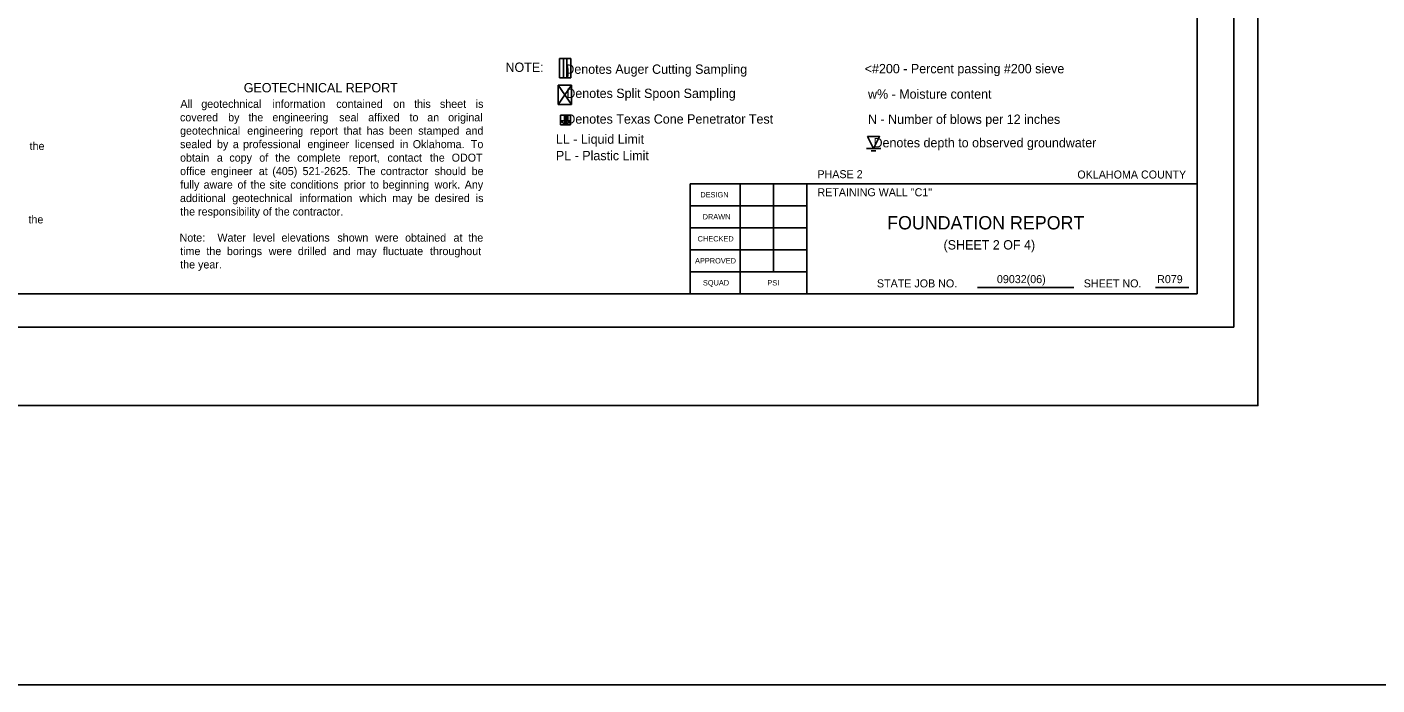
# Model space of a CAD drawing. Extents: x -6 to 173, y 24 to 64.
# Drawn here: x 65.85 to 86.09, y 25.78 to 35.64 of the extents above; entities that cross this region are included whole.
import ezdxf

# ---------------------------------------------------------------- set-up
doc = ezdxf.new("R2010")
doc.units = 0
for name, color, linetype in [('4', 7, 'Continuous'), ('S', 7, 'Continuous'), ('SHT_Plot_Shape_Full', 7, 'Continuous'), ('SHT_Plot_Shape_Half', 7, 'Continuous'), ('SHT_Sheet_Border', 7, 'Continuous'), ('SHT_Standard_Sheet_Lines', 7, 'Continuous'), ('SHT_Standard_Sheet_Txt', 7, 'Continuous'), ('T', 7, 'Continuous'), ('T-5', 7, 'Continuous'), ('Text', 7, 'Continuous')]:
    doc.layers.add(name, color=color, linetype=linetype)

# ---------------------------------------------------------------- blocks, each defined once
blk = doc.blocks.new('DGRFC_WTLEV1_1')
for points in [[(-0.005, 0), (0.005, 0)], [(0, 0), (0.00417, 0.00833), (-0.00417, 0.00833), (0, 0)], [(-0.00167, -0.00167), (0.00167, -0.00167)]]:
    blk.add_lwpolyline(points)

msp = doc.modelspace()

# ---------------------------------------------------------------- linework, layer by layer
msp.add_line((73.832, 35.172), (73.832, 34.881))
for points in [[(73.832, 35.172), (73.999, 35.172)], [(73.999, 34.881), (73.999, 35.172)], [(73.832, 34.881), (73.999, 34.881)], [(73.832, 34.881), (73.999, 34.881)]]:
    msp.add_lwpolyline(points)
for points in [[(73.891, 35.172), (73.891, 34.881), (73.941, 34.881), (73.941, 35.172)], [(73.955, 35.005), (73.949, 35.047), (73.941, 35.087), (73.955, 35.005)], [(73.941, 35.087), (73.941, 34.881), (73.955, 35.005), (73.941, 35.087)], [(73.941, 34.881), (73.955, 34.922), (73.955, 35.005), (73.941, 34.881)], [(73.941, 34.881), (73.949, 34.881), (73.955, 34.922), (73.941, 34.881)], [(73.955, 34.922), (73.957, 34.963), (73.955, 35.005), (73.955, 34.922)]]:
    msp.add_lwpolyline(points, close=True)
at = {"layer": 'S'}
msp.add_lwpolyline([(-6.024, 64.421), (172.576, 64.421), (172.576, 25.783), (-6.024, 25.783)], close=True, dxfattribs=at)
at = {"layer": 'SHT_Plot_Shape_Full'}
msp.add_lwpolyline([(48.302, 53.971), (84.302, 53.971), (84.302, 29.971), (48.302, 29.971)], close=True, dxfattribs=at)
at = {"layer": 'SHT_Plot_Shape_Half'}
msp.add_lwpolyline([(49.939, 53.146), (83.939, 53.146), (83.939, 31.146), (49.939, 31.146)], close=True, dxfattribs=at)
at = {"layer": 'SHT_Sheet_Border'}
for p, q in [((75.789, 31.646), (75.789, 33.296)), ((75.789, 33.296), (83.389, 33.296)), ((77.539, 31.646), (77.539, 33.297))]:
    msp.add_line(p, q, dxfattribs=at)
msp.add_lwpolyline([(51.889, 52.646), (83.389, 52.646), (83.389, 31.646), (51.889, 31.646)], close=True, dxfattribs=at)
at = {"layer": 'SHT_Standard_Sheet_Lines'}
for p, q in [((76.539, 31.646), (76.539, 33.297)), ((77.039, 31.976), (77.039, 33.297)), ((80.1, 31.742), (81.54, 31.742)), ((82.765, 31.742), (83.267, 31.742))]:
    msp.add_line(p, q, dxfattribs=at)
for points in [[(77.539, 32.966), (75.789, 32.966)], [(77.539, 32.636), (75.789, 32.636)], [(77.539, 32.306), (75.789, 32.306)], [(77.539, 31.976), (75.789, 31.976)]]:
    msp.add_lwpolyline(points, dxfattribs=at)
at = {"layer": 'Text'}
for p, q in [((73.809, 34.481), (73.809, 34.773)), ((73.845, 34.181), (73.845, 34.322))]:
    msp.add_line(p, q, dxfattribs=at)
for points in [[(73.809, 34.481), (74.009, 34.773)], [(73.809, 34.773), (74.009, 34.481)], [(73.809, 34.773), (74.009, 34.773)], [(74.009, 34.481), (74.009, 34.773)], [(73.809, 34.481), (74.009, 34.481)], [(73.845, 34.322), (73.995, 34.322)], [(73.995, 34.181), (73.995, 34.322)], [(73.845, 34.181), (73.995, 34.181)]]:
    msp.add_lwpolyline(points, dxfattribs=at)
for points in [[(73.905, 34.237), (73.845, 34.237), (73.92, 34.181), (73.905, 34.237)], [(73.905, 34.237), (73.935, 34.322), (73.905, 34.322), (73.905, 34.237)], [(73.905, 34.237), (73.935, 34.237), (73.935, 34.322), (73.905, 34.237)], [(73.905, 34.237), (73.92, 34.181), (73.935, 34.237), (73.905, 34.237)], [(73.92, 34.181), (73.995, 34.237), (73.935, 34.237), (73.92, 34.181)]]:
    msp.add_lwpolyline(points, close=True, dxfattribs=at)

# ---------------------------------------------------------------- block references
at = {"layer": 'Text', "xscale": 21.6, "yscale": 21.6}
msp.add_blockref('DGRFC_WTLEV1_1', (78.54, 33.823), dxfattribs=at)

# ---------------------------------------------------------------- texts
at = {"layer": '4'}
msp.add_text('FOUNDATION REPORT', height=0.2, dxfattribs=at).set_placement((78.743, 32.611))
at = {"layer": 'SHT_Standard_Sheet_Txt'}
for s, height, p in [('DESIGN', 0.08, (75.942, 33.091)), ('DRAWN', 0.08, (75.977, 32.761)), ('CHECKED', 0.08, (75.902, 32.431)), ('APPROVED', 0.08, (75.863, 32.101)), ('SQUAD', 0.08, (75.981, 31.771)), ('PSI', 0.08, (76.947, 31.771)), ('STATE JOB NO.', 0.12, (78.59, 31.742)), ('SHEET NO. ', 0.12, (81.691, 31.742))]:
    msp.add_text(s, height=height, dxfattribs=at).set_placement(p)
at = {"layer": 'T'}
for s, p in [('PHASE 2', (77.698, 33.379)), ('OKLAHOMA COUNTY', (81.595, 33.374)), ('RETAINING WALL "C1" ', (77.698, 33.108)), ('09032(06)', (80.389, 31.806)), ('R079', (82.791, 31.806))]:
    msp.add_text(s, height=0.12, dxfattribs=at).set_placement(p)
at = {"layer": 'T-5'}
msp.add_text('(SHEET 2 OF 4)', height=0.14, dxfattribs=at).set_placement((79.589, 32.31))
at = {"layer": 'Text'}
for s, height, p in [('NOTE:', 0.14, (73.021, 34.972)), ('    Denotes Auger Cutting Sampling', 0.14, (73.71, 34.943)), (' <#200 - Percent passing #200 sieve', 0.14, (78.355, 34.951)), ('GEOTECHNICAL REPORT', 0.14, (69.097, 34.665)), ('    Denotes Split Spoon Sampling', 0.14, (73.725, 34.581)), ('w% - Moisture content', 0.14, (78.456, 34.57)), ('All', 0.12, (68.147, 34.433)), ('geotechnical', 0.12, (68.46, 34.433)), ('information', 0.12, (69.528, 34.433)), ('contained', 0.12, (70.484, 34.433)), ('on', 0.12, (71.338, 34.433)), ('this', 0.12, (71.651, 34.433)), ('sheet', 0.12, (72.038, 34.433)), ('is ', 0.12, (72.575, 34.433)), ('covered', 0.12, (68.141, 34.231)), ('by', 0.12, (68.863, 34.231)), ('the', 0.12, (69.167, 34.231)), ('engineering', 0.12, (69.526, 34.231)), ('seal', 0.12, (70.528, 34.231)), ('affixed', 0.12, (70.962, 34.231)), ('to', 0.12, (71.582, 34.231)), ('an', 0.12, (71.848, 34.231)), ('original ', 0.12, (72.161, 34.231)), ('    Denotes Texas Cone Penetrator Test', 0.14, (73.725, 34.196)), ('N - Number of blows per 12 inches', 0.14, (78.456, 34.193)), ('geotechnical', 0.12, (68.142, 34.031)), ('engineering', 0.12, (69.149, 34.031)), ('report', 0.12, (70.09, 34.031)), ('that', 0.12, (70.594, 34.031)), ('has', 0.12, (70.939, 34.031)), ('been', 0.12, (71.275, 34.031)), ('stamped', 0.12, (71.713, 34.031)), ('and ', 0.12, (72.422, 34.031)), (' LL - Liquid Limit', 0.14, (73.725, 33.895)), ('the ', 0.12, (65.886, 33.801)), ('sealed', 0.12, (68.142, 33.829)), ('by', 0.12, (68.696, 33.829)), ('a', 0.12, (68.933, 33.829)), ('professional', 0.12, (69.087, 33.829)), ('engineer', 0.12, (70.051, 33.829)), ('licensed', 0.12, (70.766, 33.829)), ('in', 0.12, (71.441, 33.829)), ('Oklahoma.', 0.12, (71.631, 33.829)), ('To ', 0.12, (72.502, 33.829)), ('    Denotes depth to observed groundwater', 0.14, (78.331, 33.841)), ('obtain', 0.12, (68.142, 33.627)), ('a', 0.12, (68.693, 33.627)), ('copy', 0.12, (68.881, 33.627)), ('of', 0.12, (69.33, 33.627)), ('the', 0.12, (69.57, 33.627)), ('complete', 0.12, (69.898, 33.627)), ('report,', 0.12, (70.672, 33.627)), ('contact', 0.12, (71.251, 33.627)), ('the', 0.12, (71.887, 33.627)), ('ODOT ', 0.12, (72.214, 33.627)), (' PL - Plastic Limit', 0.14, (73.725, 33.648)), ('office', 0.12, (68.142, 33.425)), ('engineer', 0.12, (68.605, 33.425)), ('at', 0.12, (69.322, 33.425)), ('(405)', 0.12, (69.525, 33.425)), ('521-2625.', 0.12, (69.979, 33.425)), ('The', 0.12, (70.796, 33.425)), ('contractor', 0.12, (71.148, 33.425)), ('should', 0.12, (71.958, 33.425)), ('be ', 0.12, (72.514, 33.425)), ('fully', 0.12, (68.146, 33.223)), ('aware', 0.12, (68.495, 33.223)), ('of', 0.12, (69.002, 33.223)), ('the', 0.12, (69.199, 33.223)), ('site', 0.12, (69.483, 33.223)), ('conditions', 0.12, (69.795, 33.223)), ('prior', 0.12, (70.601, 33.223)), ('to', 0.12, (70.99, 33.223)), ('beginning', 0.12, (71.18, 33.223)), ('work.', 0.12, (71.958, 33.223)), ('Any ', 0.12, (72.41, 33.223)), ('additional', 0.12, (68.141, 33.021)), ('geotechnical', 0.12, (68.925, 33.021)), ('information', 0.12, (69.933, 33.021)), ('which', 0.12, (70.828, 33.021)), ('may', 0.12, (71.323, 33.021)), ('be', 0.12, (71.706, 33.021)), ('desired', 0.12, (71.959, 33.021)), ('is ', 0.12, (72.575, 33.021)), ('the ', 0.12, (65.869, 32.701)), ('the responsibility of the contractor.', 0.12, (68.144, 32.819)), ('Note:', 0.12, (68.135, 32.428)), ('Water', 0.12, (68.702, 32.428)), ('level', 0.12, (69.235, 32.428)), ('elevations', 0.12, (69.663, 32.428)), ('shown', 0.12, (70.501, 32.428)), ('were', 0.12, (71.069, 32.428)), ('obtained', 0.12, (71.516, 32.428)), ('at', 0.12, (72.242, 32.428)), ('the ', 0.12, (72.465, 32.428)), ('time', 0.12, (68.144, 32.226)), ('the', 0.12, (68.537, 32.226)), ('borings', 0.12, (68.845, 32.226)), ('were', 0.12, (69.471, 32.226)), ('drilled', 0.12, (69.909, 32.226)), ('and', 0.12, (70.432, 32.226)), ('may', 0.12, (70.787, 32.226)), ('fluctuate', 0.12, (71.18, 32.226)), ('throughout ', 0.12, (71.889, 32.226)), ('the year.', 0.12, (68.144, 32.026))]:
    msp.add_text(s, height=height, dxfattribs=at).set_placement(p)

doc.saveas('drawing.dxf')
